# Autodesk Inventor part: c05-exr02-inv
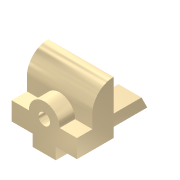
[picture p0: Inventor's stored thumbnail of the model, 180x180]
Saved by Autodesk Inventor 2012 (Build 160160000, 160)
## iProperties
Shininess: 65.0
Length Units: 11269
Angle Units: 11279
Time Units: 11290
Mass Units: 11283
Length Display Precision: 3
Angle Display Precision: 2
Created: 2001-11
Part Number: c05-exr02-inv
Document SubType Name: Modeling
Designer: Renu Muthoo
Density: 1 g/cm^3
Material: Default
Density: 0.0
Volumn: 0.0
Area: 0.0
PropertySet Name: Model Information
Control State: 0
Master: False
Checked Out: False
Author: Renu Muthoo
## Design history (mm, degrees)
node "Sketch1"
sketch "Sketch2"
  geometry: L1 (-68, 4)-(-68, -8); L2 (-68, -8)-(27, -8); L3 (27, -8)-(21, 4); L4 (21, 4)-(-68, 4)
  constraints: 8 end point, 1 horizontal, 1 perpendicular, 1 vertical
  dimensions: "d0" = 95 distance of L1.end L2.end; "d1" = 6 horizontal distance of L2.end L3.end; "d2" = 12 vertical distance of L2.end L3.end
extrude "Extrusion1" new body sketch "Sketch2" stored distance "d3" = 24; taper "d4" = 0 deg
sketch "Sketch3"
  geometry: L1 (-68, 4)-(-30, 4); L2 (-30, 4)-(-30, 59); L3 (-52, 37)-(-52, 23); L4 (-52, 23)-(-68, 23); L5 (-68, 23)-(-68, 4); L6 (-68, 4)-(21, 4) reference; L7 (-68, -8)-(-68, 4) reference; A1 r 22 centre (-30, 37) between (-30, 59) and (-52, 37)
  constraints: 10 end point, 3 parallel, 2 collinear, 2 point on circle, 1 centre point, 1 horizontal, 1 perpendicular, 1 point on line, 1 tangent
  dimensions: "d5" = 55 distance of L1.end L2.end; "d6" = 38 distance of L1.start L1.end; "d7" = 22 distance between parallel lines of L2 L3; "d8" = 19 distance of L4.end L1.start
extrude "Extrusion2" join sketch "Sketch3" stored distance "d9" = 68; taper "d10" = 0 deg
sketch "Sketch4"
  geometry: L1 (-4, 31)-(28, 31); L2 (-22, 31)-(46, 31) reference; L3 (46, 12)-(46, 31) reference; A1 r 16 centre (12, 31) between (28, 31) and (-4, 31)
  constraints: 2 end point, 2 point on circle, 1 centre point, 1 collinear, 1 horizontal
  dimensions: "d11" = 16 radius of A1; "d12" = 34 distance from line of L3 A1.centre
extrude "Extrusion3" join sketch "Sketch4" stored distance "d13" = 58; taper "d14" = 0 deg
sketch "Sketch5"
  geometry: C1 r 6 at (12, 31); 1 further point
  constraints: 1 centre point, 1 coincident
  dimensions: "d15" = 12 diameter of C1
extrude "Extrusion4" cut sketch "Sketch5" distance "d16" = 16; taper "d17" = 0 deg
body "Solid1"
